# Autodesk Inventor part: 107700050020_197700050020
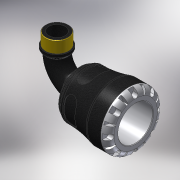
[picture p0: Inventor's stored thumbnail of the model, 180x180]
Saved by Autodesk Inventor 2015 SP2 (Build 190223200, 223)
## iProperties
Created: 2016-12
Part Number: 107700050020_197700050020
Material: PVC-Piping
Description: PLASSON 90° ELBOW WITH MALE INTEGRAL BRASS 50X2" SERIES 1
Document SubType Name: Modeling
Designer: KIM
Mass: 664.223 g
Surface Area: 733.008 cm^2
Volume: 474.445 cm^3
Density: 1.4 g/cm^3
Appearance: Black Cast
Author: KIM
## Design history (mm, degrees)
derived "1077.ipt"
feature "Solid1::1077.ipt"
tag "TaggingFeature1"
body "Solid1"
other parameters: "d1" = 33.18, "d3" = 62.5, "d4" = 85, "d8" = 72.25, "d13" = 9, "d14" = 9, "d15" = 0, "d17" = 360 deg, "d19" = 8 deg, "d20" = 1, "d21" = 1, "d22" = 8 deg, "d24" = 0, "d26" = 360 deg, "d33" = 8.5, "d43" = 66.3, "d51" = 0.85, "d54" = 17.5, "d55" = 11, "d57" = 17.64, "d58" = 0, "d74" = 0, "d78" = 79, "d82" = 1, "d115" = 360 deg, "d207" = 90 deg, "d228" = 14.875, "d247" = 1.7, "d248" = 4.74, "d268" = 39.7375, "d269" = 4.74, "d270" = 116, "d276" = 59.614, "d277" = 26, "d278" = 65.5754, "d279" = 85, "d280" = 33.8, "d281" = 8.9421, "d283" = 53.6526, "d286" = 0, "d287" = 0, "d288" = 41.7298, "d290" = 6.3237, "d292" = 30 deg, "d294" = 5.9614, "d296" = 30 deg, "E_" = 85, "l_" = 79, "A_" = 116, "A_1" = 85, "l_2" = 26, "R_" = 59.614, "d9" = 11.25, "d11" = 85, "d12" = 62.5, "d289" = 41.7298
